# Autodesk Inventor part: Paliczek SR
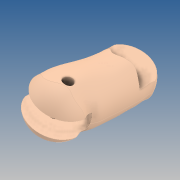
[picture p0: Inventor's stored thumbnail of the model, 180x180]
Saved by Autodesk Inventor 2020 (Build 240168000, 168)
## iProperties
Created: 2019-10
Part Number: Paliczek SR
Material: GFRP
Document SubType Name: Modeling
Designer: yello
Density: 1.75 g/cm^3
Appearance: Default
Author: yello
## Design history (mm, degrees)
feature "Paliczek SR"
sketch "Sketch1"
  geometry: C1 r 2 at (0, 0); 1 further point
  constraints: 1 centre point
  dimensions: "d0" = 4 diameter of C1
extrude "Extrusion1" cut sketch "Sketch1" stored distance "d1" = 100; taper "d2" = 0 deg
body "Solid1"
